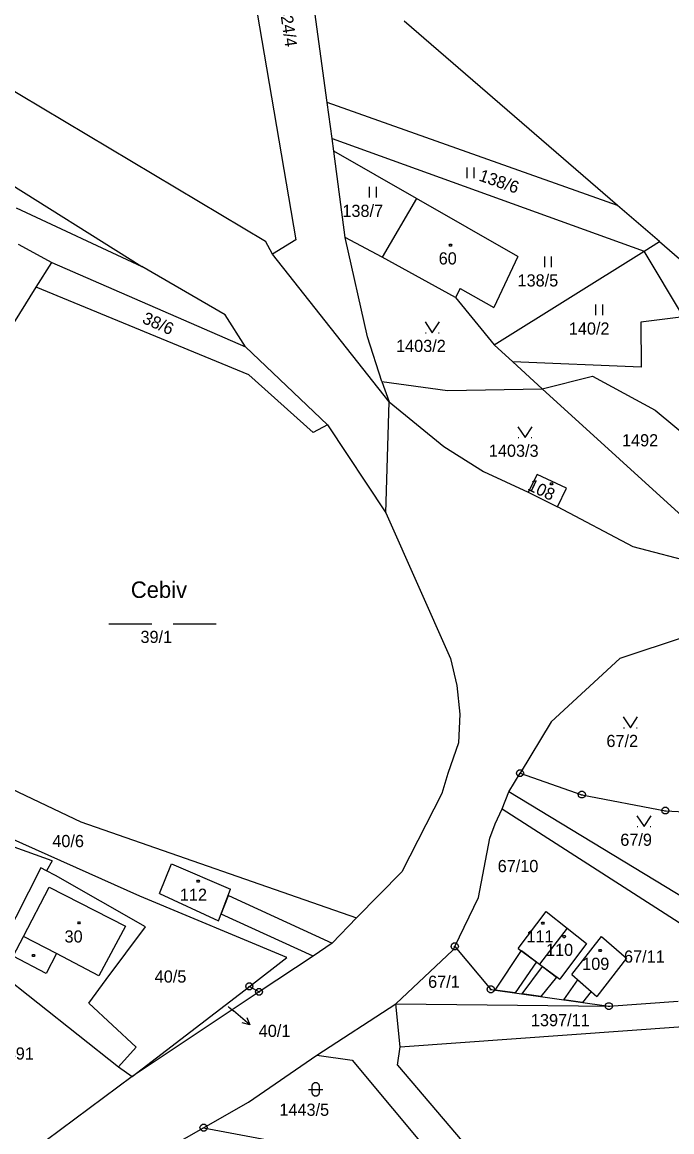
# Model space of a CAD drawing. Extents: x -850689 to -847910, y -1058374 to -1054747.
# Drawn here: x -849326.1 to -849235.3, y -1056250.1 to -1056094.9 of the extents above; entities that cross this region are included whole.
import ezdxf

# ---------------------------------------------------------------- set-up
doc = ezdxf.new("R2010")
doc.units = 0
for name, color, linetype in [('KN_BREMENA', 7, 'Continuous'), ('KN_HRANICE', 7, 'Continuous'), ('KN_KULTURY', 7, 'Continuous'), ('KN_MEZNIKY', 7, 'Continuous'), ('KN_PARCELY', 7, 'Continuous'), ('KN_SLUCKY', 7, 'Continuous'), ('KN_STAVEBNI', 7, 'Continuous')]:
    doc.layers.add(name, color=color, linetype=linetype)

# ---------------------------------------------------------------- blocks, each defined once
blk = doc.blocks.new('306')
for p, q in [((-0.5, 1.5), (-0.5, 0)), ((0.5, 0), (0.5, 1.5))]:
    blk.add_line(p, q)
blk = doc.blocks.new('314')
for p, q in [((-0.95, 0), (-0.85, 0)), ((0.85, 0), (0.95, 0))]:
    blk.add_line(p, q)
blk.add_lwpolyline([(-1, 1.5), (0, 0), (1, 1.5)])
blk = doc.blocks.new('316')
for points in [[(-0.5, 1.5), (-0.4, 1.79), (-0.15, 1.97), (0.16, 1.97), (0.41, 1.79), (0.51, 1.5), (0.51, 0.5), (0.41, 0.21), (0.16, 0.03), (-0.15, 0.03), (-0.4, 0.21), (-0.5, 0.5), (-0.5, 1.5)], [(-1, 1), (0.27, 1), (1, 1)]]:
    blk.add_lwpolyline(points)
blk = doc.blocks.new('NAHRADNI_SYMBOL')
blk.add_lwpolyline([(0.09, 0.15), (0.18, 0), (0.09, -0.15), (-0.09, -0.15), (-0.18, 0), (-0.09, 0.15), (0.09, 0.15)])
blk = doc.blocks.new('803')
for p, q in [((-7.5, 0), (-1.5, 0)), ((1.5, 0), (7.5, 0))]:
    blk.add_line(p, q)
blk = doc.blocks.new('10292')
blk.add_line((0, 3), (0, 0))
blk.add_lwpolyline([(-0.5, 2), (0, 3), (0.5, 2)])
blk = doc.blocks.new('402')
blk.add_lwpolyline([(0.09, 0.15), (0.18, 0), (0.09, -0.15), (-0.09, -0.15), (-0.18, 0), (-0.09, 0.15), (0.09, 0.15)])
blk = doc.blocks.new('105')
blk.add_line((-0.12, 0), (0.12, 0))
blk.add_lwpolyline([(0.15, 0.48), (0.4, 0.3), (0.5, 0.01), (0.4, -0.28), (0.15, -0.46), (-0.16, -0.46), (-0.41, -0.28), (-0.51, 0.01), (-0.41, 0.3), (-0.16, 0.48), (0.15, 0.48)])

msp = doc.modelspace()

# ---------------------------------------------------------------- linework, layer by layer
at = {"layer": 'KN_BREMENA'}
for points in [[(-849285.42, -1056225.55), (-849298.31, -1056219.69), (-849297.28, -1056217.06), (-849282.8, -1056223.75)], [(-849259.97, -1056230.29), (-849256.32, -1056224.78), (-849254.21, -1056226.36), (-849257.18, -1056230.68)], [(-849256.2, -1056230.82), (-849253.34, -1056227.01), (-849251.38, -1056228.47), (-849253.59, -1056231.19)], [(-849250.38, -1056231.65), (-849248.42, -1056228.87), (-849246.54, -1056230.51), (-849247.75, -1056232.02)]]:
    msp.add_lwpolyline(points, close=True, dxfattribs=at)
at = {"layer": 'KN_HRANICE'}
for p, q in [((-849447.97, -1056042.09), (-849309.42, -1056129.11)), ((-849294.47, -1056086.71), (-849287.88, -1056125.38)), ((-849283.48, -1056106.16), (-849286.11, -1056087.07)), ((-849350.5, -1056090.75), (-849292.1, -1056125.54)), ((-849242.85, -1056120.56), (-849272.71, -1056094.76)), ((-849242.85, -1056120.56), (-849283.48, -1056106.16)), ((-849282.78, -1056111.19), (-849283.48, -1056106.16)), ((-849282.53, -1056112.97), (-849282.78, -1056111.19)), ((-849282.78, -1056111.19), (-849239.16, -1056126.97)), ((-849270.99, -1056119.57), (-849282.53, -1056112.97)), ((-849280.97, -1056125.03), (-849282.53, -1056112.97)), ((-849270.99, -1056119.57), (-849275.8, -1056127.79)), ((-849256.82, -1056127.68), (-849270.99, -1056119.57)), ((-849236.99, -1056125.61), (-849242.85, -1056120.56)), ((-849326.99, -1056120.89), (-849309.42, -1056129.11)), ((-849277.82, -1056138.91), (-849280.97, -1056125.03)), ((-849275.8, -1056127.79), (-849280.97, -1056125.03)), ((-849326.68, -1056125.99), (-849322, -1056128.52)), ((-849291.12, -1056127.37), (-849292.1, -1056125.54)), ((-849287.88, -1056125.38), (-849291.12, -1056127.37)), ((-849239.16, -1056126.97), (-849236.99, -1056125.61)), ((-849236.99, -1056125.61), (-849229.16, -1056132.38)), ((-849274.83, -1056148), (-849291.12, -1056127.37)), ((-849265.54, -1056133.45), (-849275.8, -1056127.79)), ((-849256.82, -1056127.68), (-849260.15, -1056134.84)), ((-849260.1, -1056140.07), (-849239.16, -1056126.97)), ((-849233.63, -1056136.15), (-849239.16, -1056126.97)), ((-849324.16, -1056131.97), (-849322, -1056128.52)), ((-849322, -1056128.52), (-849294.9, -1056140.33)), ((-849297.73, -1056135.84), (-849309.42, -1056129.11)), ((-849329.78, -1056140.97), (-849324.16, -1056131.97)), ((-849294.45, -1056144.27), (-849324.16, -1056131.97)), ((-849264.86, -1056132.18), (-849265.54, -1056133.45)), ((-849264.86, -1056132.18), (-849260.15, -1056134.84)), ((-849265.54, -1056133.45), (-849260.1, -1056140.07)), ((-849294.9, -1056140.33), (-849297.73, -1056135.84)), ((-849233.63, -1056136.15), (-849239.63, -1056136.86)), ((-849239.63, -1056136.86), (-849239.55, -1056143.19)), ((-849275.85, -1056145.17), (-849277.82, -1056138.91)), ((-849294.9, -1056140.33), (-849283.41, -1056151.23)), ((-849257.53, -1056142.43), (-849260.1, -1056140.07)), ((-849253.4, -1056146.22), (-849257.53, -1056142.43)), ((-849239.55, -1056143.19), (-849257.53, -1056142.43)), ((-849285.45, -1056152.29), (-849294.45, -1056144.27)), ((-849275.85, -1056145.17), (-849266.67, -1056146.43)), ((-849275.85, -1056145.17), (-849274.83, -1056148)), ((-849253.4, -1056146.22), (-849246.38, -1056144.42)), ((-849246.38, -1056144.42), (-849237.58, -1056149.18)), ((-849266.67, -1056146.43), (-849253.4, -1056146.22)), ((-849253.4, -1056146.22), (-849229.69, -1056167.78)), ((-849275.26, -1056163.54), (-849274.83, -1056148)), ((-849274.83, -1056148), (-849267.18, -1056154.29)), ((-849237.58, -1056149.18), (-849232.38, -1056153.52)), ((-849283.41, -1056151.23), (-849285.45, -1056152.29)), ((-849283.41, -1056151.23), (-849275.26, -1056163.54)), ((-849267.18, -1056154.29), (-849261.61, -1056157.77)), ((-849261.61, -1056157.77), (-849255.36, -1056160.68)), ((-849254.1, -1056158.17), (-849255.36, -1056160.68)), ((-849250.02, -1056160.08), (-849254.1, -1056158.17)), ((-849255.36, -1056160.68), (-849251.27, -1056162.69)), ((-849251.27, -1056162.69), (-849250.02, -1056160.08)), ((-849275.26, -1056163.54), (-849266.24, -1056183.94)), ((-849240.7, -1056168.28), (-849251.27, -1056162.69)), ((-849231.7, -1056170.64), (-849240.7, -1056168.28)), ((-849233.39, -1056180.87), (-849242.54, -1056183.94)), ((-849266.24, -1056183.94), (-849265.33, -1056187.72)), ((-849242.54, -1056183.94), (-849252.14, -1056192.76)), ((-849265.33, -1056187.72), (-849264.93, -1056191.7)), ((-849351.28, -1056190.95), (-849317.91, -1056206.78)), ((-849264.93, -1056191.7), (-849265.09, -1056195.72)), ((-849252.14, -1056192.76), (-849256.49, -1056199.96)), ((-849265.09, -1056195.72), (-849266.61, -1056199.99)), ((-849266.61, -1056199.99), (-849267.45, -1056202.81)), ((-849258.09, -1056202.55), (-849256.49, -1056199.96)), ((-849256.49, -1056199.96), (-849247.86, -1056202.97)), ((-849321.95, -1056212.23), (-849351.88, -1056201.36)), ((-849267.45, -1056202.81), (-849273.04, -1056213.76)), ((-849259.01, -1056204.96), (-849258.09, -1056202.55)), ((-849225.53, -1056222.34), (-849258.09, -1056202.55)), ((-849247.86, -1056202.97), (-849236.17, -1056205.21)), ((-849260, -1056207.06), (-849259.01, -1056204.96)), ((-849259.01, -1056204.96), (-849223.72, -1056227.62)), ((-849236.17, -1056205.21), (-849230.65, -1056205.54)), ((-849317.91, -1056206.78), (-849279.38, -1056220.21)), ((-849260.71, -1056209.05), (-849260, -1056207.06)), ((-849309.67, -1056217.15), (-849331, -1056207.66)), ((-849262.3, -1056217.33), (-849260.71, -1056209.05)), ((-849323.51, -1056213.18), (-849328.75, -1056223.5)), ((-849322.72, -1056213.6), (-849323.51, -1056213.18)), ((-849321.95, -1056212.23), (-849322.72, -1056213.6)), ((-849321.49, -1056214.25), (-849322.72, -1056213.6)), ((-849306.91, -1056216.78), (-849305.24, -1056212.62)), ((-849305.24, -1056212.62), (-849297, -1056216.16)), ((-849308.91, -1056221.45), (-849321.49, -1056214.25)), ((-849273.04, -1056213.76), (-849279.38, -1056220.21)), ((-849306.91, -1056216.78), (-849298.66, -1056220.6)), ((-849298.66, -1056220.6), (-849297, -1056216.16)), ((-849289.11, -1056225.75), (-849309.67, -1056217.15)), ((-849265.63, -1056224.19), (-849262.3, -1056217.33)), ((-849256.75, -1056224.46), (-849252.84, -1056219.29)), ((-849252.84, -1056219.29), (-849249.91, -1056221.62)), ((-849314.38, -1056228.83), (-849308.91, -1056221.45)), ((-849279.38, -1056220.21), (-849282.8, -1056223.75)), ((-849335.86, -1056222.66), (-849312.67, -1056241.03)), ((-849249.91, -1056221.62), (-849253.79, -1056226.67)), ((-849249.91, -1056221.62), (-849247.19, -1056223.78)), ((-849249.27, -1056228.13), (-849245.12, -1056222.81)), ((-849245.12, -1056222.81), (-849241.63, -1056225.84)), ((-849282.8, -1056223.75), (-849285.42, -1056225.55)), ((-849265.63, -1056224.19), (-849265.91, -1056224.72)), ((-849265.63, -1056224.19), (-849260.59, -1056230.2)), ((-849256.75, -1056224.46), (-849253.79, -1056226.67)), ((-849247.19, -1056223.78), (-849250.95, -1056228.79)), ((-849294.36, -1056229.78), (-849289.11, -1056225.75)), ((-849285.42, -1056225.55), (-849293.01, -1056230.55)), ((-849273.87, -1056232.24), (-849265.91, -1056224.72)), ((-849241.63, -1056225.84), (-849245.74, -1056231.21)), ((-849253.79, -1056226.67), (-849250.95, -1056228.79)), ((-849316.81, -1056232.12), (-849314.38, -1056228.83)), ((-849249.27, -1056228.13), (-849245.74, -1056231.21)), ((-849310.77, -1056242.39), (-849294.36, -1056229.78)), ((-849293.01, -1056230.55), (-849310.77, -1056242.39)), ((-849294.36, -1056229.78), (-849293.01, -1056230.55)), ((-849260.59, -1056230.2), (-849244.07, -1056232.54)), ((-849316.81, -1056232.12), (-849310.19, -1056238.3)), ((-849284.94, -1056239.39), (-849273.87, -1056232.24)), ((-849273.87, -1056232.24), (-849244.07, -1056232.54)), ((-849273.28, -1056238.25), (-849273.87, -1056232.24)), ((-849244.07, -1056232.54), (-849234.37, -1056231.86)), ((-849273.28, -1056238.25), (-849233.7, -1056235.39)), ((-849310.19, -1056238.3), (-849312.67, -1056241.03)), ((-849273.62, -1056240.78), (-849273.28, -1056238.25)), ((-849294.48, -1056245.96), (-849284.94, -1056239.39)), ((-849284.94, -1056239.39), (-849279.99, -1056240.09)), ((-849279.99, -1056240.09), (-849260.83, -1056263.03)), ((-849312.67, -1056241.03), (-849310.77, -1056242.39)), ((-849273.62, -1056240.78), (-849261.46, -1056255.12)), ((-849310.77, -1056242.39), (-849324.78, -1056252.85)), ((-849300.76, -1056249.55), (-849294.48, -1056245.96)), ((-849321.82, -1056261.46), (-849300.76, -1056249.55)), ((-849300.76, -1056249.55), (-849281.15, -1056253.26))]:
    msp.add_line(p, q, dxfattribs=at)
at = {"layer": 'KN_PARCELY'}
msp.add_line((-849297.28, -1056232.64), (-849296.59, -1056233.22), dxfattribs=at)
at = {"layer": 'KN_SLUCKY'}
for p, q in [((-849325.97, -1056222.79), (-849322.37, -1056215.9)), ((-849322.37, -1056215.9), (-849311.67, -1056221.36)), ((-849311.67, -1056221.36), (-849315.41, -1056228.3)), ((-849327.41, -1056225.56), (-849325.97, -1056222.79)), ((-849321.32, -1056225.2), (-849325.97, -1056222.79)), ((-849322.77, -1056227.98), (-849327.41, -1056225.56)), ((-849321.32, -1056225.2), (-849322.77, -1056227.98)), ((-849315.41, -1056228.3), (-849321.32, -1056225.2))]:
    msp.add_line(p, q, dxfattribs=at)
at = {"layer": 'KN_STAVEBNI'}
for p, q in [((-849254.1, -1056158.17), (-849255.36, -1056160.68)), ((-849250.02, -1056160.08), (-849254.1, -1056158.17)), ((-849255.36, -1056160.68), (-849251.27, -1056162.69)), ((-849251.27, -1056162.69), (-849250.02, -1056160.08)), ((-849306.91, -1056216.78), (-849305.24, -1056212.62)), ((-849305.24, -1056212.62), (-849297, -1056216.16)), ((-849325.97, -1056222.79), (-849322.37, -1056215.9)), ((-849322.37, -1056215.9), (-849311.67, -1056221.36)), ((-849306.91, -1056216.78), (-849298.66, -1056220.6)), ((-849298.66, -1056220.6), (-849297, -1056216.16)), ((-849256.75, -1056224.46), (-849252.84, -1056219.29)), ((-849252.84, -1056219.29), (-849249.91, -1056221.62)), ((-849311.67, -1056221.36), (-849315.41, -1056228.3)), ((-849321.32, -1056225.2), (-849325.97, -1056222.79)), ((-849249.91, -1056221.62), (-849253.79, -1056226.67)), ((-849249.91, -1056221.62), (-849253.79, -1056226.67)), ((-849249.91, -1056221.62), (-849247.19, -1056223.78)), ((-849249.27, -1056228.13), (-849245.12, -1056222.81)), ((-849245.12, -1056222.81), (-849241.63, -1056225.84)), ((-849256.75, -1056224.46), (-849253.79, -1056226.67)), ((-849247.19, -1056223.78), (-849250.95, -1056228.79)), ((-849315.41, -1056228.3), (-849321.32, -1056225.2)), ((-849241.63, -1056225.84), (-849245.74, -1056231.21)), ((-849253.79, -1056226.67), (-849250.95, -1056228.79)), ((-849249.27, -1056228.13), (-849245.74, -1056231.21))]:
    msp.add_line(p, q, dxfattribs=at)

# ---------------------------------------------------------------- block references
at = {"layer": 'KN_KULTURY'}
for name, p in [('306', (-849263.43, -1056116.73)), ('306', (-849277.1, -1056119.46)), ('NAHRADNI_SYMBOL', (-849266.22, -1056126.11)), ('306', (-849252.6, -1056129.19)), ('306', (-849245.43, -1056135.92)), ('314', (-849268.78, -1056138.35)), ('314', (-849255.8, -1056153.01)), ('402', (-849252.11, -1056159.49)), ('803', (-849306.51, -1056179.05)), ('314', (-849241.06, -1056193.6)), ('314', (-849239.16, -1056207.42)), ('402', (-849301.52, -1056215.06)), ('402', (-849318.19, -1056220.88)), ('402', (-849253.3, -1056220.93)), ('402', (-849250.32, -1056222.82)), ('402', (-849324.57, -1056225.46)), ('402', (-849245.3, -1056224.77)), ('316', (-849285.1, -1056245.18))]:
    msp.add_blockref(name, p, dxfattribs=at)
at = {"layer": 'KN_MEZNIKY'}
for p in [(-849256.49, -1056199.96), (-849247.86, -1056202.97), (-849236.17, -1056205.21), (-849265.63, -1056224.19), (-849294.36, -1056229.78), (-849293.01, -1056230.55), (-849260.59, -1056230.2), (-849244.07, -1056232.54), (-849300.76, -1056249.55)]:
    msp.add_blockref('105', p, dxfattribs=at)
at = {"layer": 'KN_PARCELY', "rotation": -130.01474100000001}
msp.add_blockref('10292', (-849296.59, -1056233.22), dxfattribs=at)

# ---------------------------------------------------------------- texts
at = {"layer": 'KN_PARCELY'}
for s, rotation, p in [('1424/4', 278.228, (-849290.34, -1056091.59)), ('138/6', 340.738, (-849262.38, -1056117.05)), ('38/6', 336.04, (-849309.47, -1056136.93)), ('108', 334.722, (-849255.57, -1056160.28))]:
    msp.add_text(s, height=1.7, rotation=rotation, dxfattribs=at).set_placement(p)
for s, height, p in [('138/7', 1.7, (-849281.35, -1056122.16)), ('60', 1.7, (-849267.88, -1056128.81)), ('138/5', 1.7, (-849256.85, -1056131.89)), ('140/2', 1.7, (-849249.68, -1056138.62)), ('1403/2', 1.7, (-849273.84, -1056141.05)), ('1492', 1.7, (-849242.24, -1056154.25)), ('1403/3', 1.7, (-849260.86, -1056155.71)), ('Cebiv', 2.3, (-849310.94, -1056175.45)), ('39/1', 1.7, (-849309.59, -1056181.75)), ('67/2', 1.7, (-849244.42, -1056196.3)), ('40/6', 1.7, (-849321.92, -1056210.3)), ('67/9', 1.7, (-849242.48, -1056210.12)), ('67/10', 1.7, (-849259.63, -1056213.8)), ('112', 1.7, (-849304.08, -1056217.81)), ('30', 1.7, (-849320.21, -1056223.65)), ('111', 1.7, (-849255.61, -1056223.63)), ('110', 1.7, (-849252.87, -1056225.52)), ('109', 1.7, (-849247.81, -1056227.47)), ('67/11', 1.7, (-849241.96, -1056226.46)), ('40/5', 1.7, (-849307.6, -1056229.25)), ('67/1', 1.7, (-849269.36, -1056229.98)), ('40/1', 0.1, (-849297.46, -1056232.64)), ('1397/11', 1.7, (-849254.98, -1056235.35)), ('40/1', 1.7, (-849293.05, -1056236.85)), ('1491', 1.7, (-849329.56, -1056240.02)), ('1443/5', 1.7, (-849290.16, -1056247.88))]:
    msp.add_text(s, height=height, dxfattribs=at).set_placement(p)

doc.saveas('drawing.dxf')
